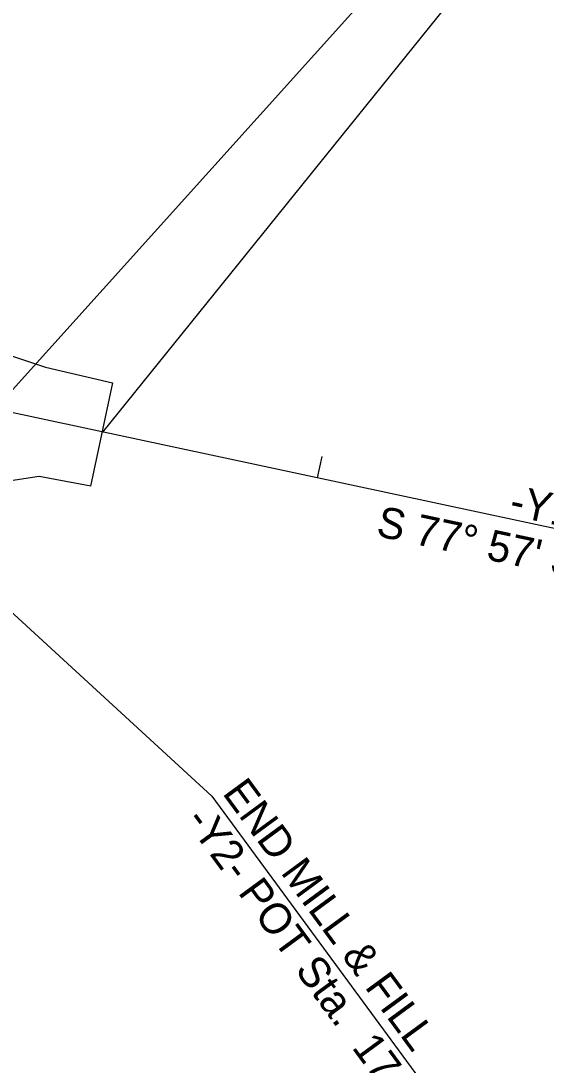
# Model space of a CAD drawing. Extents: x 1762196 to 1766326, y 709922 to 713142.
# Drawn here: x 1763916.4 to 1764035.8, y 712250.7 to 712488 of the extents above; entities that cross this region are included whole.
import ezdxf

# ---------------------------------------------------------------- set-up
doc = ezdxf.new("R2010")
doc.units = 0
for name, color, linetype in [('Prop EOT', 7, 'Continuous'), ('Prop Horizontal Alignment', 7, 'Continuous'), ('Prop Horizontal Alignment Direction Label', 7, 'Continuous'), ('Prop Horizontal Alignment Station Label', 7, 'Continuous'), ('Prop Horizontal Alignment Tick Small', 7, 'Continuous')]:
    doc.layers.add(name, color=color, linetype=linetype)

msp = doc.modelspace()

# ---------------------------------------------------------------- linework, layer by layer
at = {"layer": 'Prop EOT'}
msp.add_line((1763932.33, 712382.27), (1763937.33, 712405.73), dxfattribs=at)
for points in [[(1763913.18, 712412.33), (1763914.3, 712411.89), (1763922, 712409.27), (1763937.27, 712405.74)], [(1763932.33, 712382.27), (1763923.01, 712384.01), (1763920.57, 712384.46), (1763913.14, 712383.35), (1763909.38, 712382.51), (1763906.65, 712381.71)]]:
    msp.add_lwpolyline(points, dxfattribs=at)
at = {"layer": 'Prop Horizontal Alignment'}
msp.add_line((1764408.68, 712293.5), (1763471.86, 712493.33), dxfattribs=at)
at = {"layer": 'Prop Horizontal Alignment Station Label'}
for p, q in [((1764025.58, 712506.91), (1763934.95, 712394.55)), ((1763999.72, 712498.79), (1763910.5, 712399.76)), ((1763959.83, 712311.81), (1763865.74, 712398.25)), ((1763959.83, 712311.81), (1764029.03, 712217.65))]:
    msp.add_line(p, q, dxfattribs=at)
at = {"layer": 'Prop Horizontal Alignment Tick Small'}
msp.add_line((1763983.85, 712384.12), (1763984.89, 712389.01), dxfattribs=at)

# ---------------------------------------------------------------- texts
at = {"layer": 'Prop Horizontal Alignment Direction Label'}
for s, rotation, p in [('-Y1- ', 347.8638, (1764027.12, 712375.74)), ('S 77%%d 57\' 32.0" E', 347.9589, (1763996.89, 712371))]:
    msp.add_text(s, height=7, rotation=rotation, dxfattribs=at).set_placement(p)
at = {"layer": 'Prop Horizontal Alignment Station Label'}
for s, p in [('END MILL & FILL', (1763962.04, 712312.51)), ('-Y2- POT Sta.  17+74.00', (1763953.58, 712306.29))]:
    msp.add_text(s, height=7, rotation=306.3131, dxfattribs=at).set_placement(p)

doc.saveas('drawing.dxf')
